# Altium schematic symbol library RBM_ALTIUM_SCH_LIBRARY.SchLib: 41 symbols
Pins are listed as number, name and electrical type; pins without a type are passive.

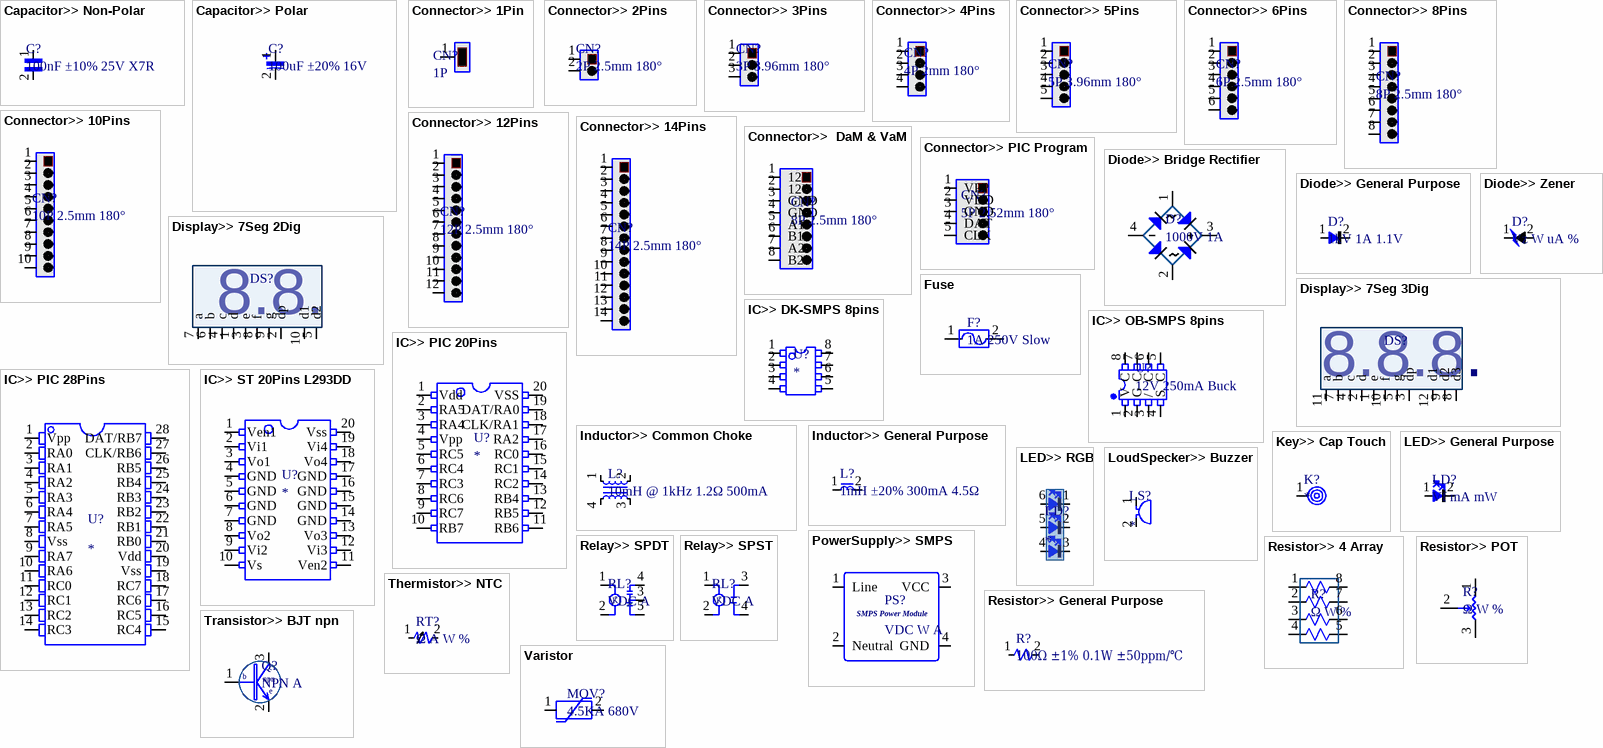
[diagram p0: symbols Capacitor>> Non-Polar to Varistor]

## Capacitor>> Non-Polar
designator C?, comment 100nF ±10% 25V X7R
footprint C_0805
footprint C_X1_P10
footprint C_X2_26X12X21.5_P22.5
footprint C_0603 (0603 Multilayer Ceramic Capacitors MLCC - SMD/SMT RoHS)
footprint C_X2_18X10X16_P15
footprint C_CY_P10 (CY1222ME1IEF46X0A2; 2.2nF ±20% 400VAC 10 Through Hole,P=10mm Suppression Capacitors RoHS)
footprint C_1206 (NM1206B104K451CEGN; 100nF ±10% 450V X7R 1206 Multilayer Ceramic Capacitors MLCC - SMD/SMT RoHS)
pins: 1, 2

## Capacitor>> Polar
designator C?, comment 100uF ±20% 16V
footprint C_Radial_Ø5*11mm_P2
footprint C_Radial_Ø5*11mm_P2_Right_Angle
footprint C_Radial_Ø5*11mm _P2_Right_Angle_without_3d
footprint C_Radial_Ø6.3*11mm_P2.5
footprint C_Radial_Ø8*11mm_P3.5
footprint C_SMD_Ø4*5.4mm
footprint C_SMD_Ø5*5.4mm
footprint C_SMD_Ø6.3*5.4mm (SMD 6.3x5.4mm Aluminum Electrolytic Capacitors - SMD RoHS)
footprint C_SMD_Ø8*10mm (VKMD1002G4R7MV; 4.7uF ±20% 400V SMD,8x10mm Aluminum Electrolytic Capacitors - SMD RoHS)
footprint C_SMD_Ø10*13mm (Aluminum Electrolytic Capacitor, Body 10.30x10.30x13.50mm, IPC Low Density)
pins: 1, 2

## Connector>> 1Pin
designator CN?, comment 1P
footprint CN_Tab Terminal 187 series (Right Angle)
footprint CN_Tab Terminal 187 series (Straight)
footprint CN_Tab Terminal 250 series (Right Angle)
footprint CN_Tab Terminal 250 series (Straight)
footprint CN_Ø1.25mm_Lead (Lead Wire)
pins: 1

## Connector>> 2Pins
designator CN?, comment 2P 2.5mm 180°
footprint CN_B2B-XH-A_RED
footprint CN_B2B-XH-A_WHITE
footprint CN_PIC_MCU_Reseter_Straight
footprint CN_B2P-VH_BLUE (3.96mm Pitch)
footprint CN_B3P-VH_BLUE_AC (3.96mm Pitch)
pins: 1, 2

## Connector>> 3Pins
designator CN?, comment 3P 3.96mm 180°
footprint CN_B3P-VH_BLUE_DC (3.96mm Pitch)
pins: 1, 2, 3

## Connector>> 4Pins
designator CN?, comment 4P 2mm 180°
footprint CN_4P_A2001WR-S-XP-LCP
footprint CN_4P_A2001WV-XP-180DEG (Top Entry Header 1.25mm pitch 1X4pin  180° long)
pins: 1, 2, 3, 4

## Connector>> 5Pins
designator CN?, comment 5P 3.96mm 180°
footprint CN_B5P-VH_BLUE (3.96mm Pitch)
pins: 1, 2, 3, 4, 5

## Connector>> 6Pins
designator CN?, comment 6P 2.5mm 180°
footprint CN_B6B-XH-A_BLUE (2.5mm Pitch, 8pins, Top-Entry, XH Connector)
pins: 1, 2, 3, 4, 5, 6

## Connector>> 8Pins
designator CN?, comment 8P 2.5mm 180°
footprint CN_B8B-XH-A_BLUE (2.5mm Pitch, 8pins, Top-Entry, XH Connector)
pins: 1, 2, 3, 4, 5, 6, 7, 8

## Connector>> 10Pins
designator CN?, comment 10P 2.5mm 180°
footprint CN_B10B-XH-A_BLUE (2.5mmPitch, TopEntry, BlueColor, XH Connector)
pins: 1, 2, 3, 4, 5, 6, 7, 8, 9, 10

## Connector>> 12Pins
designator CN?, comment 12P 2.5mm 180°
footprint CN_B12B-XH-A_BLUE (2.5mmPitch, TopEntry, BlueColor, XH Connector)
pins: 1, 2, 3, 4, 5, 6, 7, 8, 9, 10, 11, 12

## Connector>> 14Pins
designator CN?, comment 14P 2.5mm 180°
footprint CN_B14B-XH-A_BLUE (2.5mmPitch, TopEntry, BlueColor, XH Connector)
pins: 1, 2, 3, 4, 5, 6, 7, 8, 9, 10, 11, 12, 13, 14

## Connector>>  DaM & VaM
designator CN?, comment 8P 2.5mm 180°
footprint CN_B8B-XH-A_BLUE
pins: 1 12V, 2 12V, 3 GND, 4 GND, 5 A1, 6 B1, 7 A2, 8 B2

## Connector>> PIC Program
designator CN?, comment 5P 2.52mm 180°
footprint CN_PIC_MCU_Debugger_RightAngle
footprint CN_PIC_MCU_Debugger_Straight
pins: 1 VPP, 2 VDD, 3 GND, 4 DAT, 5 CLK

## Diode>> Bridge Rectifier
designator D?, comment 1000V 1A
footprint D_SMD_ABS10
footprint D_SMD_MBS
pins: 1 AC, 2 AC, 3 VCC, 4 vss

## Diode>> General Purpose
designator D?, comment 1kV 1A 1.1V
footprint D_SOT-23-3_200mA (Diodes - General Purpose 100V 200mA 1.25V @ 200mA SOT-23(SOT-23-3) RoHS)
footprint D_DO-214AC (RS1M; 1000V 1A 1.3V @ 1A 500ns SMA Diodes - Rectifiers - Fast Recovery RoHS)
pins: 1 A, 2 K

## Diode>> Zener
designator D?, comment Vz W uA %
footprint D_SMD_LL-41
pins: 1 A, 2 K

## Display>> 7Seg 2Dig
designator DS?  (value not drawn)
footprint DS_56" 2 digit Display
pins: 1 d, 2 dp, 3 e, 4 c, 5 d2, 6 b, 7 a, 8 f, 9 g, 10 d1

## Display>> 7Seg 3Dig
designator DS?  (value not drawn)
footprint DS_0.36"_3DIG (SLR0363DWC1BD)
footprint DS_0.56"_3DIG
pins: 1 e, 2 d, 3 dp, 4 c, 5 g, 7 b, 8 d3, 9 d2, 10 f, 11 a, 12 d1

## Fuse
designator F?, comment 1A 250V Slow
footprint F_Radial_Ø8.5*8_P5.08 (37011000000; Through Hole,P=5.08mm Fuses with Leads (Through Hole) RoHS)
footprint F_SQUARE_8.5*8_P5.08 (Littelfuse 39211000440; TE5 Time-Lag Fuse)
pins: 1, 2

## IC>> DK-SMPS 8pins
designator U?
footprint U_DK912_TH
pins: 1, 2, 3, 4, 5, 6, 7, 8

## IC>> OB-SMPS 8pins
designator U?, comment 12V 250mA Buck
footprint U_SOP-8 (SOP, 8-Leads, Body 4.90x3.90mm, Pitch 1.27mm, Thermal Pad 2.00x1.20mm, IPC Medium Density)
pins: 1 V, 2 G, 3 /, 4 S, 5 C, 6 C, 7 C, 8 C

## IC>> PIC 20Pins
designator U?
footprint U_PIC_20Pin_SOIC (SOIC, 20-Leads, Body 12.80x7.50mm, Pitch 1.27mm, IPC Medium Density)
footprint U_PIC_20pin_SSOP (SOP, 20-Leads, Body 7.20x5.30mm, Pitch 0.65mm, IPC Medium Density)
pins: 1 Vdd, 2 RA5, 3 RA4, 4 Vpp, 5 RC5, 6 RC4, 7 RC3, 8 RC6, 9 RC7, 10 RB7, 11 RB6, 12 RB5, 13 RB4, 14 RC2, 15 RC1, 16 RC0, 17 RA2, 18 CLK/RA1, 19 DAT/RA0, 20 VSS

## IC>> PIC 28Pins
designator U?
footprint U_PIC16F18856_SSOP (SOP, 28-Leads, Body 10.20x5.30mm, Pitch 0.65mm, Thermal Pad 8.00x4.00mm, IPC Medium Density)
pins: 1 Vpp, 2 RA0, 3 RA1, 4 RA2, 5 RA3, 6 RA4, 7 RA5, 8 Vss, 9 RA7, 10 RA6, 11 RC0, 12 RC1, 13 RC2, 14 RC3, 15 RC4, 16 RC5, 17 RC6, 18 RC7, 19 Vss, 20 Vdd, 21 RB0, 22 RB1, 23 RB2, 24 RB3, 25 RB4, 26 RB5, 27 CLK/RB6, 28 DAT/RB7

## IC>> ST 20Pins L293DD
designator U?
footprint U_L293DD (SOIC, 20-Leads, Body 12.80x7.50mm, Pitch 1.27mm, Thermal Pad 9.00x4.60mm, IPC Medium Density)
pins: 1 Ven1, 2 Vi1, 3 Vo1, 4 GND, 5 GND, 6 GND, 7 GND, 8 Vo2, 9 Vi2, 10 Vs, 11 Ven2, 12 Vi3, 13 Vo3, 14 GND, 15 GND, 16 GND, 17 GND, 18 Vo4, 19 Vi4, 20 Vss

## Inductor>> Common Choke
designator L?, comment 10mH @ 1kHz 1.2Ω 500mA
footprint L_CMC_7x8mm (1~22mH, 1000~200mA)
pins: 1, 2, 3, 4

## Inductor>> General Purpose
designator L?, comment 1mH ±20% 300mA 4.5Ω
footprint L_6x10_P3
footprint L_SMD_6.0x6.0x4.5mm (YNR6045-102M;  1mH ±20% 300mA 4.5O SMD,6.0x6.0x4.5mm Power Inductors RoHS)
pins: 1, 2

## Key>> Cap Touch
designator K?
footprint K_Cap-Touch_10H-8W-0.6D
footprint K_Cap-Touch_12H-9W-0.6&1.3D
footprint K_Cap-Touch_15H-8W-0.5D
footprint K_Cap-Touch-Round_LED
footprint K_Cap-Touch-Square_LED
pins: 1

## LED>> General Purpose
designator LD?, comment Vf mA mW
footprint LED_3x5_P2.5
footprint LED_SMD3528
footprint LED_SMD2835
footprint LED_SMD0603
footprint LED_4.8x5.8_P2.54 (HL-798H256WC-MD)
pins: 1 vdd, 2 vss

## LED>> RGB
designator LD?
footprint LED_PLCC5050 (EDISON RGB .2W)
pins: 1, 2, 3, 4, 5, 6

## LoudSpecker>> Buzzer
designator LS?
footprint LS_12.2x6.5_P5_PS1240P02BT
pins: 1 vdd, 2 vss

## PowerSupply>> SMPS
designator PS?, comment VDC W A
footprint PS_HP03S1200WJ_SMPS_12VDC-3W
footprint PS_ZP10S1200W_SMPS_12VDC-10W
pins: 1 Line, 2 Neutral, 3 VCC, 4 GND

## Relay>> SPDT
designator RL?, comment VDC A
footprint RL_SPDT_10ARelay_AZ943-1CH-12DE
pins: 1, 2, 3 COM, 4 NO, 5 NC

## Relay>> SPST
designator RL?, comment VDC A
footprint RL_SPST_5ARelay_AZ7709-1AB-12DE
footprint RL_SPST_15ARelay_AZ943-1AH-12DE
pins: 1, 2, 3, 4

## Resistor>> 4 Array
designator R?, comment Ω W %
footprint R_0603_4_array (Chip Array, Concave, 8-Leads, Pitch 0.80mm,  Body 3.20x1.60mm,  IPC Medium Density)
pins: 1, 2, 3, 4, 5, 6, 7, 8

## Resistor>> General Purpose
designator R?, comment 100Ω ±1% 0.1W ±50ppm/℃
footprint R_0805
footprint R_1206
footprint R_2512 (Chip Resistor, 2-Leads, Body 6.35x3.10mm, IPC Medium Density)
footprint R_Axial_P15 (Resistors 12mm Length)
footprint R_Axial_P10 (Resistors 7mm Length)
footprint R_Axial_P13 (Resistors 10.5mm Length)
footprint R_Radial_P5 (All Through Hole Resistors)
footprint R_1812 (Chip Resistor, 2-Leads, Body 4.50x3.00mm, IPC Medium Density)
footprint R_0603 (RK73G1JTTD1000F; 0603 Chip Resistor - Surface Mount RoHS)
pins: 1, 2

## Resistor>> POT
designator R?, comment Ω W %
footprint R_POT
pins: 1 VDD, 2 POT, 3 VSS

## Thermistor>> NTC
designator RT?, comment Ω A W %
footprint NTC_5mmPitch
pins: 1, 2

## Transistor>> BJT npn
designator Q?, comment NPN A
footprint Q_SOT-23_NPN (NPN 200mA 40V 250mW SOT-23(SOT-23-3))
pins: 1 Base, 2 Emitter, 3 Collector

## Varistor
designator MOV?, comment 4.5KA 680V
footprint MOV_10D471
footprint MOV_14D561K
pins: 1, 2

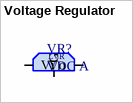
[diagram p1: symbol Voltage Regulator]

## Voltage Regulator
designator VR?, comment VDC A
footprint VR_SOT89 (SOT89, 3-Leads, Body 4.50x2.45mm, Pitch 1.50mm, Lead Span 4.1mm - Reverse Pinning, IPC Medium Density)
footprint VR_TO-252-2(DPAK) (D-PAK, 3-Pads, Body 6.20x6.61mm (max), IPC Medium Density)
pins: GND G, V-IN Vi, V-OUT Vo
